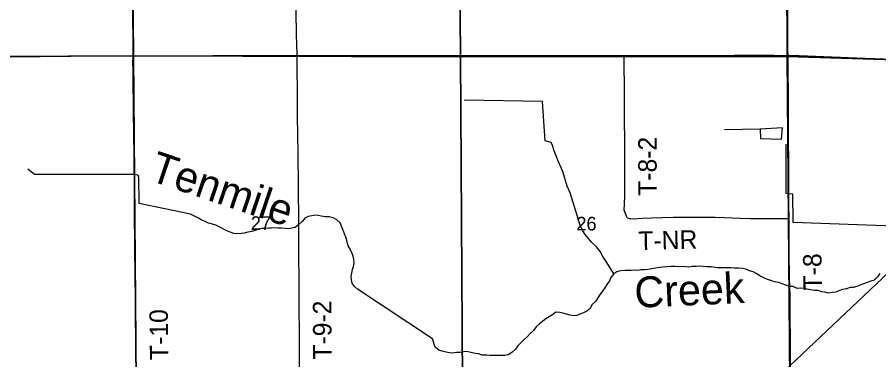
# Model space of a CAD drawing. Extents: x 0 to 34, y 0 to 22.
# Drawn here: x 25.546 to 28.195, y 16.699 to 17.753 of the extents above; entities that cross this region are included whole.
import ezdxf

# ---------------------------------------------------------------- set-up
doc = ezdxf.new("R2010")
doc.units = 0
for name, color, linetype in [('GM_X_Minor_Lake', 7, 'Continuous'), ('GM_X_Minor_River', 7, 'Continuous'), ('GM_X_Minor_River_Text', 7, 'Continuous'), ('GM_X_Rail_Line', 7, 'Continuous'), ('GM_X_Section', 7, 'Continuous'), ('GM_X_Section_Text', 7, 'Continuous'), ('GM_X_State_Route', 7, 'Continuous'), ('GM_X_Township_Road', 7, 'Continuous'), ('GM_X_Township_Road_Text', 7, 'Continuous'), ('GM_X_US_Route', 7, 'Continuous')]:
    doc.layers.add(name, color=color, linetype=linetype)

msp = doc.modelspace()

# ---------------------------------------------------------------- linework, layer by layer
at = {"layer": 'GM_X_Minor_Lake'}
msp.add_line((27.8306, 17.4084), (27.8315, 17.3799), dxfattribs=at)
msp.add_lwpolyline([(27.8315, 17.3799), (27.8963, 17.3778), (27.8993, 17.4123), (27.8306, 17.4084)], dxfattribs=at)
at = {"layer": 'GM_X_Minor_River'}
for points in [[(27.3802, 16.9632), (27.372, 16.9773), (27.3594, 16.9983), (27.3471, 17.017), (27.3385, 17.0323), (27.3269, 17.0461), (27.3119, 17.0614), (27.3026, 17.0718), (27.2925, 17.0844), (27.285, 17.0958), (27.2761, 17.1153), (27.2688, 17.1396), (27.2461, 17.2131), (27.2369, 17.2329), (27.2237, 17.2782), (27.2104, 17.3079), (27.2034, 17.3266), (27.1975, 17.3422), (27.192, 17.3582), (27.1876, 17.367), (27.1691, 17.3725), (27.1613, 17.494), (26.9206, 17.4979)], [(27.8306, 17.4084), (27.7207, 17.4061)], [(28.3273, 17.1071), (27.9317, 17.1217), (27.9304, 17.2089), (27.9107, 17.2107), (27.9105, 17.3621)], [(26.0789, 17.1473), (25.9215, 17.1803), (25.9198, 17.2623), (25.9172, 17.2669), (25.913, 17.2684), (25.9039, 17.2693), (25.5991, 17.2692), (25.5792, 17.2858)], [(26.5926, 16.916), (26.5829, 16.9241), (26.5765, 16.9348), (26.5736, 16.9447), (26.5734, 16.9557), (26.575, 16.9655), (26.5774, 16.9765), (26.5798, 16.9863), (26.5822, 16.9977), (26.5815, 17.0072), (26.5794, 17.0178), (26.5749, 17.0281), (26.5698, 17.0392), (26.5642, 17.0499), (26.5609, 17.0609), (26.5587, 17.0708), (26.5543, 17.0811), (26.5477, 17.1001), (26.5388, 17.1199), (26.5287, 17.1299), (26.5181, 17.1353), (26.5049, 17.1385), (26.4928, 17.139), (26.481, 17.1414), (26.4712, 17.1426), (26.4614, 17.1435), (26.4519, 17.1421), (26.4405, 17.1403), (26.4302, 17.1343), (26.4221, 17.1241), (26.4114, 17.114), (26.4006, 17.1057), (26.3904, 17.1036), (26.3801, 17.1018), (26.3699, 17.1026), (26.3589, 17.1039), (26.3487, 17.104), (26.3388, 17.1052), (26.3282, 17.1038), (26.3184, 17.1043), (26.3089, 17.1032), (26.2986, 17.1033), (26.2888, 17.1004), (26.2781, 17.0971), (26.2674, 17.0942), (26.2553, 17.0916), (26.2443, 17.0891), (26.2344, 17.088), (26.2245, 17.0866), (26.212, 17.0875), (26.2011, 17.0914), (26.1905, 17.0961), (26.1671, 17.1081), (26.157, 17.1135), (26.1464, 17.1166), (26.1347, 17.1198), (26.1241, 17.124), (26.1143, 17.1283), (26.1041, 17.1352), (26.0789, 17.1473)], [(27.7519, 16.9808), (27.7413, 16.982), (27.7315, 16.9817), (27.7208, 16.9815), (27.7102, 16.9823), (27.7004, 16.9824), (27.6905, 16.9833), (27.6796, 16.9849), (27.6655, 16.9854), (27.6546, 16.9859), (27.6443, 16.9868), (27.6337, 16.9861), (27.6216, 16.9859), (27.6109, 16.9844), (27.6007, 16.9853), (27.5909, 16.9858), (27.5795, 16.9851), (27.5681, 16.9856), (27.5564, 16.9861), (27.5427, 16.9847), (27.5313, 16.9841), (27.5215, 16.9831), (27.5082, 16.9809), (27.4968, 16.9788), (27.4846, 16.977), (27.4747, 16.9763), (27.4637, 16.9757), (27.4543, 16.9742), (27.4433, 16.9743), (27.4334, 16.9737), (27.4239, 16.9734), (27.4141, 16.9739), (27.4023, 16.9725), (27.3901, 16.9699), (27.3802, 16.9632), (27.3717, 16.9519), (27.3667, 16.9417), (27.3594, 16.9304), (27.3524, 16.9206), (27.3455, 16.9104), (27.3386, 16.9006), (27.3308, 16.8893), (27.3239, 16.878), (27.3128, 16.8679), (27.3074, 16.8573), (27.2974, 16.8483), (27.2871, 16.8435), (27.2764, 16.839), (27.2669, 16.8353), (27.2574, 16.8343), (27.2461, 16.8359), (27.2351, 16.8391), (27.2238, 16.8426), (27.214, 16.845), (27.2022, 16.8458), (27.1923, 16.8376), (27.182, 16.8312), (27.1717, 16.8253), (27.1621, 16.8182), (27.1518, 16.8095), (27.1418, 16.8001), (27.1333, 16.7896), (27.1234, 16.7798), (27.1145, 16.7701), (27.105, 16.7618), (27.0954, 16.7524), (27.085, 16.7419), (27.0777, 16.7321), (27.0674, 16.7212), (27.0555, 16.7141), (27.0457, 16.7123), (27.0305, 16.7128), (27.0206, 16.7122), (27.01, 16.7127), (27.0005, 16.7124), (26.9896, 16.7132), (26.9752, 16.7138), (26.9653, 16.7177), (26.9544, 16.7189), (26.9404, 16.7217), (26.9286, 16.7245), (26.918, 16.7238), (26.9078, 16.7213), (26.8971, 16.7214), (26.8858, 16.7192), (26.8751, 16.7201), (26.8646, 16.7221), (26.8525, 16.7252), (26.8423, 16.7291), (26.8317, 16.738), (26.8277, 16.7475), (26.8251, 16.757), (26.8229, 16.7635)], [(28.1983, 16.9646), (28.191, 16.954), (28.1803, 16.9442), (28.1708, 16.9406), (28.1593, 16.9369), (28.1479, 16.9324), (28.1373, 16.9291), (28.127, 16.925), (28.1163, 16.9217), (28.1065, 16.9211), (28.0958, 16.9174), (28.0837, 16.9152), (28.0726, 16.9115), (28.0627, 16.9071), (28.0521, 16.9061), (28.0403, 16.9039), (28.0294, 16.9067), (28.0195, 16.9083), (28.0089, 16.9126), (27.9976, 16.9123), (27.9851, 16.9143), (27.9753, 16.9167), (27.965, 16.9179), (27.9537, 16.9196), (27.9438, 16.9189), (27.9318, 16.9247), (27.9204, 16.9248), (27.9094, 16.9284), (27.8981, 16.9326), (27.8875, 16.9365), (27.8747, 16.9389), (27.8626, 16.9432), (27.8528, 16.9464), (27.8411, 16.951), (27.8298, 16.9576), (27.8181, 16.9649), (27.8083, 16.9696), (27.7973, 16.9727), (27.786, 16.9781), (27.7747, 16.9802), (27.7633, 16.9807), (27.7519, 16.9808)], [(26.8229, 16.7635), (26.5926, 16.916)]]:
    msp.add_lwpolyline(points, dxfattribs=at)
at = {"layer": 'GM_X_Rail_Line'}
msp.add_lwpolyline([(27.0345, 15.3175), (27.0356, 15.4259), (27.0494, 15.5562), (27.0656, 15.6449), (27.0886, 15.7152), (27.1197, 15.8028), (27.1531, 15.872), (27.1854, 15.9273), (27.2223, 15.9838), (27.2614, 16.0437), (27.3144, 16.1048), (27.4089, 16.2005), (27.94, 16.6983), (28.7611, 17.4753), (29.4921, 18.1638), (30.1262, 18.7537), (30.3167, 18.9329)], dxfattribs=at)
at = {"layer": 'GM_X_Section'}
for points in [[(24.8949, 18.6346), (25.8948, 18.6366), (25.9035, 17.634), (24.9025, 17.6286)], [(25.8948, 18.6366), (26.901, 18.6343), (26.9089, 17.6314), (25.9035, 17.634)], [(26.901, 18.6343), (27.9094, 18.6339), (27.9132, 17.6317), (26.9089, 17.6314)], [(27.9094, 18.6339), (28.9031, 18.5906), (28.914, 17.6074), (28.9139, 17.6013), (27.9132, 17.6317)], [(24.9025, 17.6286), (25.9035, 17.634), (25.9123, 16.6303), (24.9155, 16.6278)], [(25.9035, 17.634), (26.9089, 17.6314), (26.9154, 16.6284), (25.9123, 16.6303)], [(26.9089, 17.6314), (27.9132, 17.6317), (27.9213, 16.6311), (26.9154, 16.6284)], [(27.9132, 17.6317), (28.9139, 17.6013), (28.9274, 16.6074), (28.9273, 16.6021), (27.9213, 16.6311)]]:
    msp.add_lwpolyline(points, close=True, dxfattribs=at)
at = {"layer": 'GM_X_State_Route'}
for points in [[(26.9096, 17.635), (26.9094, 17.655), (26.9085, 17.7701), (26.9083, 17.8012), (26.9083, 17.8111), (26.9082, 17.8353), (26.9065, 17.9628), (26.9055, 18.0809), (26.9042, 18.1835), (26.9037, 18.2208), (26.9015, 18.4664), (26.8999, 18.6187), (26.8998, 18.6366), (26.8995, 18.6685), (26.8989, 18.8457), (26.8988, 18.8923), (26.8987, 18.9451), (26.8983, 18.9886), (26.8978, 19.0539), (26.8976, 19.1565), (26.8966, 19.4239)], [(26.9163, 16.6335), (26.9156, 16.7255), (26.9146, 16.8436), (26.9142, 16.94), (26.9118, 17.3037), (26.9114, 17.3877), (26.9108, 17.484), (26.9096, 17.635)]]:
    msp.add_lwpolyline(points, dxfattribs=at)
at = {"layer": 'GM_X_Township_Road'}
for points in [[(27.916, 17.6355), (27.9156, 17.6507), (27.9153, 17.7626), (27.9149, 17.8559), (27.9148, 17.8838), (27.9146, 17.9274), (27.9144, 18.0175), (27.9131, 18.1263), (27.9122, 18.1729), (27.9118, 18.2288), (27.9113, 18.3594), (27.9106, 18.4246), (27.9102, 18.4961), (27.9096, 18.5831), (27.9088, 18.636), (27.9087, 18.6372)], [(25.9025, 17.6344), (25.9026, 17.6548), (25.9024, 17.6703), (25.9022, 17.7605), (25.9014, 17.8911), (25.9, 18.0715), (25.9, 18.0837)], [(26.4066, 17.6348), (26.4065, 17.638), (26.405, 17.7001), (26.4027, 17.8429), (26.402, 17.8802), (26.4012, 17.9022)], [(25.9122, 16.63), (25.9123, 16.6409), (25.9123, 16.6596), (25.9115, 16.7218), (25.9101, 16.8711), (25.91, 16.9022), (25.9093, 16.9426), (25.9083, 17.0576), (25.9074, 17.1447), (25.9066, 17.2349), (25.9057, 17.3002), (25.9057, 17.3127), (25.9055, 17.3345), (25.9051, 17.3842), (25.9042, 17.4744), (25.9031, 17.5584), (25.9024, 17.5895), (25.9022, 17.6144), (25.9024, 17.6299), (25.9025, 17.6344)], [(26.4137, 16.6316), (26.4139, 16.6383), (26.4144, 16.6539), (26.4141, 16.7253), (26.4132, 16.9147), (26.4124, 17.0514), (26.412, 17.1011), (26.4108, 17.2532), (26.4101, 17.3122), (26.4096, 17.3339), (26.4081, 17.4486), (26.4082, 17.4672), (26.4081, 17.4952), (26.407, 17.6225), (26.4066, 17.6348)], [(27.4217, 17.1362), (27.4125, 17.1596), (27.4131, 17.1783), (27.4138, 17.2033), (27.4144, 17.2659), (27.4141, 17.341), (27.4138, 17.3617), (27.4144, 17.3771), (27.4134, 17.4332), (27.4133, 17.452), (27.4129, 17.5238), (27.4128, 17.5518), (27.4124, 17.5924), (27.4123, 17.6174), (27.4122, 17.6236), (27.4119, 17.6349)], [(27.9191, 17.1337), (27.9186, 17.1752), (27.9183, 17.2685), (27.9178, 17.4177), (27.9172, 17.4798), (27.9163, 17.6259), (27.916, 17.6355)], [(27.4217, 17.1362), (27.4248, 17.1347), (27.4278, 17.1338), (27.4309, 17.1334), (27.4402, 17.1332), (27.4681, 17.1344), (27.496, 17.1355), (27.5643, 17.1376), (27.5653, 17.1376)], [(27.5653, 17.1376), (27.6263, 17.1383), (27.6915, 17.1378), (27.7194, 17.1369), (27.769, 17.1348), (27.8, 17.1342), (27.8466, 17.1338), (27.9191, 17.1337)], [(27.9219, 16.634), (27.9221, 16.6407), (27.9232, 16.6997), (27.9233, 16.7526), (27.9229, 16.8365), (27.9222, 16.8955), (27.921, 16.9515), (27.9199, 17.026), (27.9194, 17.054), (27.9193, 17.1193), (27.9191, 17.1337)]]:
    msp.add_lwpolyline(points, dxfattribs=at)
at = {"layer": 'GM_X_US_Route'}
for points in [[(25.5236, 17.6313), (25.8033, 17.6338), (25.9025, 17.6344), (25.9183, 17.6344), (25.9524, 17.6343), (25.9773, 17.6344), (26.1482, 17.6347), (26.1918, 17.6347), (26.3627, 17.6347), (26.4066, 17.6348), (26.4436, 17.6348)], [(26.4436, 17.6348), (26.6486, 17.6347), (26.8158, 17.6352), (26.9096, 17.635)], [(26.9096, 17.635), (26.9581, 17.635), (27.0332, 17.6348), (27.095, 17.6348), (27.1262, 17.6349), (27.3284, 17.6352), (27.3938, 17.6349), (27.4119, 17.6349), (27.4218, 17.635), (27.4591, 17.6353), (27.5214, 17.6354), (27.7516, 17.6357), (27.8232, 17.6358), (27.873, 17.636), (27.916, 17.6355), (27.9507, 17.6348), (28.1529, 17.6272), (28.2679, 17.623), (28.4152, 17.6177), (28.4514, 17.6164), (28.6411, 17.6096), (28.7406, 17.6059), (28.7727, 17.6045)]]:
    msp.add_lwpolyline(points, dxfattribs=at)

# ---------------------------------------------------------------- texts
at = {"layer": 'GM_X_Minor_River_Text'}
for s, rotation, p in [('Tenmile', 341.3083, (25.9481, 17.2524)), ('Creek', 2.5646, (27.4459, 16.8589))]:
    msp.add_text(s, height=0.09477, rotation=rotation, dxfattribs=at).set_placement(p)
at = {"layer": 'GM_X_Section_Text'}
for s, p in [('27', (26.2644, 17.0985)), ('26', (27.2652, 17.0969))]:
    msp.add_text(s, height=0.04186, rotation=0, dxfattribs=at).set_placement(p)
at = {"layer": 'GM_X_Township_Road_Text'}
for s, rotation, p in [('T-8-2', 90, (27.5122, 17.2035)), ('T-NR', 1.4617, (27.4564, 17.0367)), ('T-8', 90.9539, (28.0205, 16.9129)), ('T-9-2', 90.3014, (26.513, 16.6998)), ('T-10', 90.7083, (26.0113, 16.6988))]:
    msp.add_text(s, height=0.05682, rotation=rotation, dxfattribs=at).set_placement(p)

doc.saveas('drawing.dxf')
